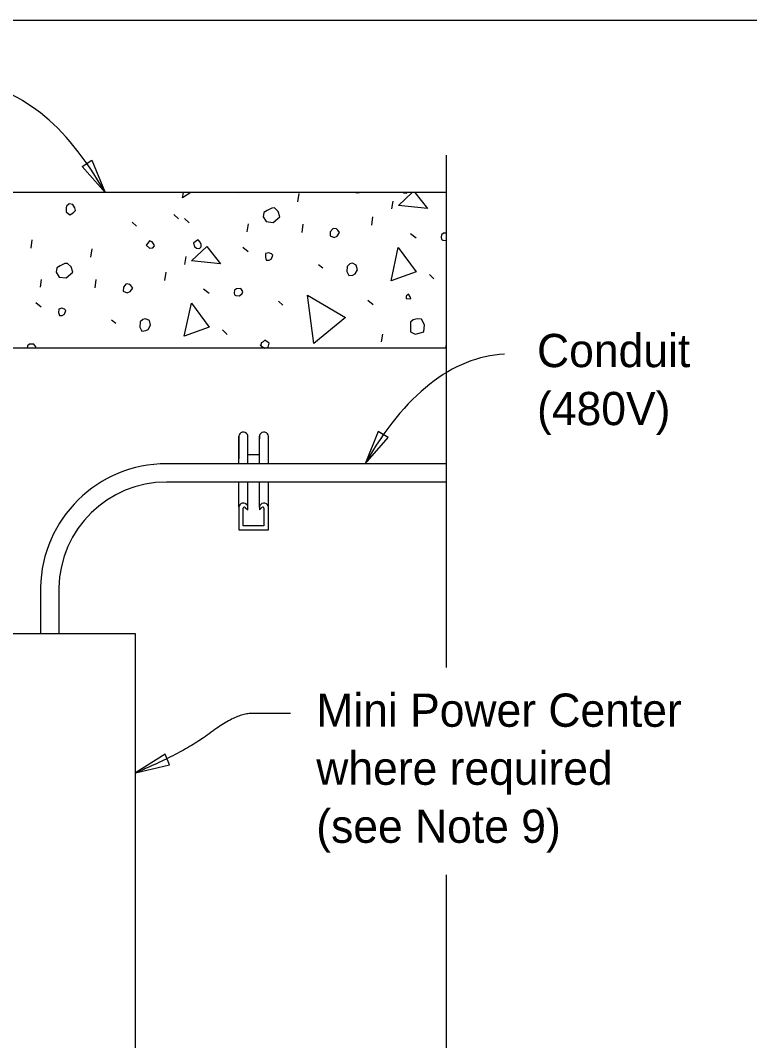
# Model space of a CAD drawing. Extents: x 112544 to 112597.1, y 111084 to 111107.1.
# Drawn here: x 112560.031 to 112563.349, y 111100.721 to 111105.363 of the extents above; entities that cross this region are included whole.
import ezdxf

# ---------------------------------------------------------------- set-up
doc = ezdxf.new("R2010")
doc.units = 0
for name, color, linetype in [('ActivePts-ConstElements', 7, 'Continuous'), ('Dimension', 7, 'Continuous'), ('Lighting', 7, 'Continuous'), ('Miscellaneous', 7, 'Continuous'), ('SupstrConc', 7, 'Continuous')]:
    doc.layers.add(name, color=color, linetype=linetype)

msp = doc.modelspace()

# ---------------------------------------------------------------- linework, layer by layer
at = {"layer": 'ActivePts-ConstElements'}
msp.add_lwpolyline([(112543.9918, 111085.9039), (112574.7797, 111085.9039), (112574.7797, 111105.3634), (112543.9918, 111105.3634)], close=True, dxfattribs=at)
at = {"layer": 'Dimension'}
for points in [[(112561.9699, 111102.4193), (112561.9699, 111104.7499)], [(112561.9699, 111095.8655), (112561.9699, 111100.3037), (112561.8924, 111100.3037), (112561.9699, 111100.3375), (112562.0474, 111100.3712), (112561.9699, 111100.3712), (112561.9699, 111101.4759)]]:
    msp.add_lwpolyline(points, dxfattribs=at)
for points in [[(112560.4156, 111104.5802), (112560.3109, 111104.6991), (112560.3559, 111104.7269)], [(112561.5993, 111103.3459), (112561.7039, 111103.4648), (112561.6589, 111103.4926)], [(112560.5547, 111101.9393), (112560.709, 111101.9752), (112560.6886, 111102.0241)]]:
    msp.add_lwpolyline(points, close=True, dxfattribs=at)
for centre, major_axis, start_param, end_param in [((112559.6704, 111102.7114), (-0.1111, -2.3674), 2.502126, 3.141581), ((112562.3445, 111101.4771), (0.1111, -2.3674), 3.141604, 3.781128)]:
    msp.add_ellipse(centre, major_axis=major_axis, ratio=0.464296, start_param=start_param, end_param=end_param, dxfattribs=at)
msp.add_open_spline([(112561.2591, 111102.21), (112561.1519, 111102.21), (112561.0141, 111102.21), (112560.7742, 111102.0312), (112560.5547, 111101.9393)], degree=2, dxfattribs=at)
at = {"layer": 'Lighting'}
for p, q in [((112561.0242, 111103.3459), (112561.0242, 111103.4709)), ((112561.0242, 111103.4709), (112561.0242, 111103.3683)), ((112561.0658, 111103.4752), (112561.0636, 111103.4791)), ((112561.0658, 111103.4592), (112561.0658, 111103.4752)), ((112561.0658, 111103.3459), (112561.0658, 111103.4709)), ((112561.1201, 111103.4791), (112561.118, 111103.4752)), ((112561.118, 111103.4752), (112561.118, 111103.4592)), ((112561.118, 111103.3459), (112561.118, 111103.4709)), ((112561.1596, 111103.3459), (112561.1596, 111103.4709)), ((112561.9699, 111103.3459), (112560.6952, 111103.3459)), ((112561.118, 111103.3869), (112561.0658, 111103.3869)), ((112561.9699, 111103.2627), (112560.6952, 111103.2627)), ((112561.0242, 111103.148), (112561.0242, 111103.2627)), ((112561.0658, 111103.148), (112561.0658, 111103.2627)), ((112561.118, 111103.148), (112561.118, 111103.2627)), ((112561.1596, 111103.148), (112561.1596, 111103.2627)), ((112561.0242, 111103.148), (112561.0242, 111103.0454)), ((112561.045, 111103.064), (112561.045, 111103.1436)), ((112561.0539, 111103.1469), (112561.0658, 111103.1363)), ((112561.0658, 111103.1523), (112561.0636, 111103.1562)), ((112561.0658, 111103.1363), (112561.0658, 111103.1523)), ((112561.1201, 111103.1562), (112561.118, 111103.1523)), ((112561.118, 111103.1523), (112561.118, 111103.1363)), ((112561.118, 111103.1363), (112561.1299, 111103.1469)), ((112561.1388, 111103.1436), (112561.1388, 111103.064)), ((112561.1596, 111103.0454), (112561.1596, 111103.148)), ((112561.0242, 111103.0454), (112561.1596, 111103.0454)), ((112561.1388, 111103.064), (112561.045, 111103.064)), ((112560.1223, 111102.7825), (112560.1223, 111102.5734)), ((112560.2056, 111102.7818), (112560.2056, 111102.5734))]:
    msp.add_line(p, q, dxfattribs=at)
msp.add_lwpolyline([(112559.6884, 111099.8484), (112559.5529, 111099.8484), (112559.5529, 111102.5734), (112560.5529, 111102.5734), (112560.5529, 111099.8484), (112560.4174, 111099.8484)], dxfattribs=at)
for radius, end in [(0.5729, 179.0565), (0.4896, 178.9794)]:
    msp.add_arc((112560.6952, 111102.7731), radius, 90, end, dxfattribs=at)
for centre, major_axis, start_param, end_param in [((112561.045, 111103.4709), (-0.0208, 0), 3.598509, 6.283184), ((112561.1388, 111103.4709), (0.0208, 0), 0.000002, 2.684677), ((112561.045, 111103.148), (-0.0208, 0), 3.598509, 6.283184), ((112561.1388, 111103.148), (0.0208, 0), 0.000002, 2.684677), ((112561.0502, 111103.1436), (-0.0052, 0), 3.926991, 6.283185), ((112561.1336, 111103.1436), (0.0052, 0), 6.283185, 8.63938)]:
    msp.add_ellipse(centre, major_axis=major_axis, ratio=0.8951, start_param=start_param, end_param=end_param, dxfattribs=at)
at = {"layer": 'Miscellaneous'}
for p, q in [((112561.0206, 111104.5794), (112561.0208, 111104.5803)), ((112561.293, 111104.5385), (112561.2984, 111104.5761)), ((112561.7211, 111104.5056), (112561.7272, 111104.5409)), ((112560.7288, 111104.4805), (112560.7498, 111104.4602)), ((112560.7776, 111104.4625), (112560.7986, 111104.4422)), ((112561.6295, 111104.4319), (112561.635, 111104.4696)), ((112560.539, 111104.4451), (112560.5593, 111104.4273)), ((112561.063, 111104.4018), (112561.0691, 111104.4371)), ((112561.3123, 111104.3987), (112561.3178, 111104.4364)), ((112561.8054, 111104.3937), (112561.8312, 111104.3747)), ((112560.0789, 111104.327), (112560.0843, 111104.3647)), ((112560.3512, 111104.2861), (112560.3567, 111104.3238)), ((112561.043, 111104.3317), (112561.0664, 111104.3121)), ((112560.7793, 111104.2533), (112560.7854, 111104.2886)), ((112561.3876, 111104.2532), (112561.4072, 111104.2378)), ((112560.1213, 111104.1494), (112560.1273, 111104.1847)), ((112560.3706, 111104.1464), (112560.376, 111104.184)), ((112560.6878, 111104.1796), (112560.6932, 111104.2173)), ((112561.8917, 111104.2071), (112561.9126, 111104.1868)), ((112560.8637, 111104.1413), (112560.8895, 111104.1223)), ((112561.6122, 111104.0908), (112561.6356, 111104.0712)), ((112560.1012, 111104.0794), (112560.1246, 111104.0597)), ((112561.2048, 111104.0852), (112561.2251, 111104.0673)), ((112560.4458, 111104.0009), (112560.4654, 111103.9854)), ((112560.9499, 111103.9548), (112560.9708, 111103.9345)), ((112561.6737, 111103.9002), (112561.6797, 111103.9355))]:
    msp.add_line(p, q, dxfattribs=at)
for points in [[(112560.7682, 111104.5557), (112560.7734, 111104.5803)], [(112560.8063, 111104.5803), (112560.7682, 111104.5557)], [(112561.5576, 111104.5803), (112561.5592, 111104.5787), (112561.5743, 111104.5802), (112561.5744, 111104.5803)], [(112561.7505, 111104.5213), (112561.814, 111104.5803)], [(112561.8262, 111104.5803), (112561.8836, 111104.5078), (112561.7505, 111104.5213)], [(112561.7726, 111104.5803), (112561.7738, 111104.5793), (112561.7872, 111104.5777), (112561.7901, 111104.5803)], [(112560.2395, 111104.5098), (112560.2392, 111104.4916), (112560.2558, 111104.478), (112560.2714, 111104.4873), (112560.2816, 111104.4978), (112560.2783, 111104.5099), (112560.269, 111104.5255), (112560.2525, 111104.5288), (112560.24, 111104.5177), (112560.2395, 111104.5098)], [(112561.1353, 111104.4703), (112561.149, 111104.4481), (112561.1812, 111104.4438), (112561.2105, 111104.4698), (112561.204, 111104.4939), (112561.1868, 111104.51), (112561.174, 111104.5092), (112561.1536, 111104.4985), (112561.138, 111104.4892), (112561.1353, 111104.4703)], [(112561.4408, 111104.4021), (112561.4405, 111104.3839), (112561.4583, 111104.3757), (112561.4721, 111104.382), (112561.4834, 111104.3979), (112561.4753, 111104.4087), (112561.4685, 111104.4147), (112561.4576, 111104.4169), (112561.4527, 111104.4156), (112561.4408, 111104.4021)], [(112561.9699, 111104.3952), (112561.9552, 111104.395), (112561.9468, 111104.3875), (112561.9446, 111104.3766), (112561.9472, 111104.3669)], [(112561.9472, 111104.3669), (112561.9533, 111104.3634), (112561.9691, 111104.3624), (112561.9699, 111104.3631)], [(112560.6032, 111104.3407), (112560.6174, 111104.3264), (112560.6325, 111104.3278), (112560.6402, 111104.3377), (112560.6389, 111104.3425), (112560.6302, 111104.3557), (112560.6186, 111104.3603), (112560.6109, 111104.3505), (112560.6032, 111104.3407)], [(112560.8088, 111104.2689), (112560.8792, 111104.3344), (112560.9418, 111104.2554), (112560.8088, 111104.2689)], [(112560.8222, 111104.3347), (112560.832, 111104.3269), (112560.8454, 111104.3254), (112560.8538, 111104.3328), (112560.8536, 111104.3431), (112560.848, 111104.3545), (112560.8399, 111104.3653), (112560.8267, 111104.3566), (112560.8183, 111104.3492), (112560.8222, 111104.3347)], [(112561.7181, 111104.1787), (112561.7501, 111104.3297), (112561.8314, 111104.2194), (112561.7181, 111104.1787)], [(112561.1456, 111104.2867), (112561.1495, 111104.2722), (112561.1622, 111104.2731), (112561.1737, 111104.2787), (112561.1794, 111104.2958), (112561.1727, 111104.3017), (112561.1611, 111104.3064), (112561.1466, 111104.3025), (112561.1456, 111104.2867)], [(112560.1935, 111104.218), (112560.2072, 111104.1958), (112560.2394, 111104.1914), (112560.2687, 111104.2174), (112560.2622, 111104.2416), (112560.245, 111104.2576), (112560.2323, 111104.2568), (112560.2118, 111104.2462), (112560.1962, 111104.2368), (112560.1935, 111104.218)], [(112561.5169, 111104.2439), (112561.5155, 111104.2202), (112561.5255, 111104.2022), (112561.543, 111104.2043), (112561.5544, 111104.2099), (112561.5651, 111104.2283), (112561.5592, 111104.25), (112561.5415, 111104.2582), (112561.5294, 111104.255), (112561.5169, 111104.2439)], [(112560.4991, 111104.1497), (112560.4988, 111104.1315), (112560.5165, 111104.1233), (112560.5303, 111104.1296), (112560.5416, 111104.1456), (112560.5335, 111104.1564), (112560.5268, 111104.1623), (112560.5158, 111104.1646), (112560.511, 111104.1633), (112560.4991, 111104.1497)], [(112561.0054, 111104.1146), (112561.0115, 111104.111), (112561.0273, 111104.1101), (112561.0399, 111104.1212), (112561.0428, 111104.1298), (112561.034, 111104.143), (112561.0134, 111104.1426), (112561.0051, 111104.1352), (112561.0028, 111104.1242), (112561.0054, 111104.1146)], [(112561.3651, 111103.8926), (112561.3372, 111104.1129), (112561.5093, 111104.0115), (112561.3651, 111103.8926)], [(112561.7862, 111104.0986), (112561.8074, 111104.0965), (112561.8048, 111104.1062), (112561.7968, 111104.117), (112561.786, 111104.1089), (112561.7862, 111104.0986)], [(112560.2039, 111104.0344), (112560.2077, 111104.0199), (112560.2205, 111104.0207), (112560.2319, 111104.0264), (112560.2377, 111104.0434), (112560.2309, 111104.0494), (112560.2193, 111104.0541), (112560.2048, 111104.0502), (112560.2039, 111104.0344)], [(112560.7763, 111103.9264), (112560.8084, 111104.0773), (112560.8896, 111103.9671), (112560.7763, 111103.9264)], [(112560.5751, 111103.9915), (112560.5737, 111103.9678), (112560.5837, 111103.9498), (112560.6012, 111103.9519), (112560.6127, 111103.9576), (112560.6233, 111103.976), (112560.6175, 111103.9977), (112560.5997, 111104.0059), (112560.5877, 111104.0026), (112560.5751, 111103.9915)], [(112561.805, 111103.9898), (112561.8063, 111103.9461), (112561.8271, 111103.9362), (112561.8392, 111103.9394), (112561.8657, 111103.9465), (112561.87, 111103.9787), (112561.8557, 111104.0034), (112561.8368, 111104.0061), (112561.8175, 111104.0009), (112561.805, 111103.9898)], [(112561.1245, 111103.8825), (112561.1429, 111103.8719), (112561.1574, 111103.8758), (112561.1625, 111103.8953), (112561.1435, 111103.9083), (112561.1351, 111103.9009), (112561.1261, 111103.8959), (112561.1245, 111103.8825), (112561.1232, 111103.8873)], [(112560.0991, 111103.8718), (112560.101, 111103.8774), (112560.0923, 111103.8906), (112560.0717, 111103.8903), (112560.0633, 111103.8828), (112560.0611, 111103.8719), (112560.0611, 111103.8718)], [(112561.9658, 111103.8718), (112561.9699, 111103.8906)]]:
    msp.add_lwpolyline(points, dxfattribs=at)
at = {"layer": 'SupstrConc'}
for p, q in [((112561.9699, 111104.5803), (112556.9271, 111104.5803)), ((112561.9699, 111103.8718), (112556.9271, 111103.8718))]:
    msp.add_line(p, q, dxfattribs=at)

# ---------------------------------------------------------------- texts
at = {"layer": 'Dimension'}
for s, p in [('Conduit', (112562.3817, 111103.7856)), ('(480V)', (112562.3817, 111103.5216)), ('Mini Power Center', (112561.377, 111102.1491)), ('where required', (112561.377, 111101.8851)), ('(see Note 9)', (112561.377, 111101.6211))]:
    msp.add_text(s, height=0.1512, dxfattribs=at).set_placement(p)

doc.saveas('drawing.dxf')
